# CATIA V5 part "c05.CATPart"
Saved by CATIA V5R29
Part number: c05
Source: Unknown
Bounding box of the stored display mesh (mm): x 16.662 to 134.073, y -101 to 75, z 102.292 to 225.053
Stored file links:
  C:\Users\Administrator\Desktop\프로젝트\Boxfold\TapeCutter\c05.CATPart
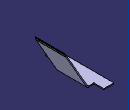
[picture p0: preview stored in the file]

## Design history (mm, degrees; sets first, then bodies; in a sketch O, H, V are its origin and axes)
Body1 (main body)
  Solid1 "PartBody": solid without history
